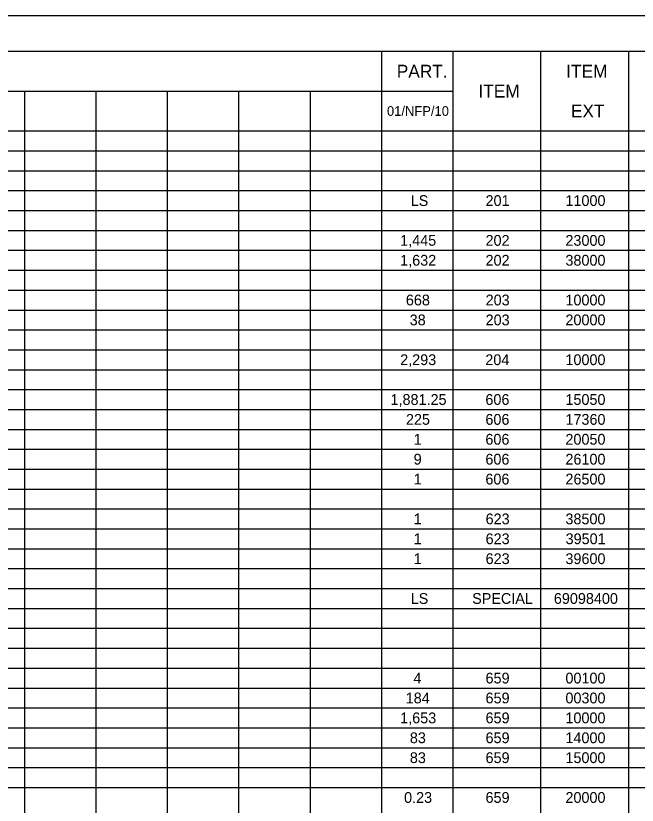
# Model space of a CAD drawing. Extents: x -31.7 to 37.3, y 0 to 22.
# Drawn here: x 9.42 to 18.16, y 10.89 to 22 of the extents above; entities that cross this region are included whole.
import ezdxf

# ---------------------------------------------------------------- set-up
doc = ezdxf.new("R2010")
doc.units = 0
for name, color, linetype in [('SH_Border', 7, 'Continuous'), ('SH_Cut_Line', 7, 'Continuous'), ('SH_Data', 7, 'Continuous'), ('SH_Text', 7, 'Continuous')]:
    doc.layers.add(name, color=color, linetype=linetype)

msp = doc.modelspace()

# ---------------------------------------------------------------- linework, layer by layer
at = {"layer": 'SH_Border'}
msp.add_lwpolyline([(1.5, 21.5), (33.5, 21.5), (33.5, 0.5), (1.5, 0.5)], close=True, dxfattribs=at)
at = {"layer": 'SH_Cut_Line'}
msp.add_lwpolyline([(0, 0), (34, 0), (34, 22), (0, 22)], close=True, dxfattribs=at)
at = {"layer": 'SH_Data'}
for p, q in [((1.5, 21.5), (32.001, 21.5)), ((14.56, 21.5), (14.56, 0.502)), ((15.565, 21.5), (15.565, 0.502)), ((16.8, 21.5), (16.8, 0.502)), ((18.035, 21.5), (18.035, 0.502)), ((1.5, 20.94), (15.565, 20.94)), ((9.537, 20.94), (9.537, 0.502)), ((10.542, 20.94), (10.542, 0.502)), ((11.546, 20.94), (11.546, 0.502)), ((12.551, 20.94), (12.551, 0.502)), ((13.556, 20.94), (13.556, 0.502)), ((1.5, 20.38), (32.001, 20.38)), ((1.5, 20.1), (32.001, 20.1)), ((1.5, 19.82), (32.001, 19.82)), ((1.5, 19.54), (32.001, 19.54)), ((1.5, 19.26), (32.001, 19.26)), ((1.5, 18.98), (32.001, 18.98)), ((1.5, 18.7), (32.001, 18.7)), ((1.5, 18.42), (32.001, 18.42)), ((1.5, 18.14), (32.001, 18.14)), ((1.5, 17.86), (32.001, 17.86)), ((1.5, 17.58), (32.001, 17.58)), ((1.5, 17.3), (32.001, 17.3)), ((1.5, 17.02), (32.001, 17.02)), ((1.5, 16.74), (32.001, 16.74)), ((1.5, 16.46), (32.001, 16.46)), ((1.5, 16.18), (32.001, 16.18)), ((1.5, 15.9), (32.001, 15.9)), ((1.5, 15.62), (32.001, 15.62)), ((1.5, 15.34), (32.001, 15.34)), ((1.5, 15.061), (32.001, 15.061)), ((1.5, 14.781), (32.001, 14.781)), ((1.5, 14.501), (32.001, 14.501)), ((1.5, 14.221), (32.001, 14.221)), ((1.5, 13.941), (32.001, 13.941)), ((1.5, 13.661), (32.001, 13.661)), ((1.5, 13.381), (32.001, 13.381)), ((1.5, 13.101), (32.001, 13.101)), ((1.5, 12.821), (32.001, 12.821)), ((1.5, 12.541), (32.001, 12.541)), ((1.5, 12.261), (32.001, 12.261)), ((1.5, 11.981), (32.001, 11.981)), ((1.5, 11.701), (32.001, 11.701)), ((1.5, 11.421), (32.001, 11.421)), ((1.5, 11.141), (32.001, 11.141))]:
    msp.add_line(p, q, dxfattribs=at)

# ---------------------------------------------------------------- texts
at = {"layer": 'SH_Text'}
for s, height, p in [('PART.', 0.1818, (14.776, 21.129)), ('ITEM', 0.1818, (17.16, 21.129)), ('ITEM', 0.1818, (15.925, 20.849)), ('01/NFP/10', 0.1364, (14.638, 20.592)), ('EXT', 0.1818, (17.226, 20.569)), ('LS', 0.1515, (14.972, 19.324)), ('201', 0.1515, (16.025, 19.324)), ('11000', 0.1515, (17.149, 19.324)), ('1,445', 0.1515, (14.824, 18.764)), ('202', 0.1515, (16.025, 18.764)), ('23000', 0.1515, (17.149, 18.764)), ('1,632', 0.1515, (14.824, 18.484)), ('202', 0.1515, (16.025, 18.484)), ('38000', 0.1515, (17.149, 18.484)), ('668', 0.1515, (14.904, 17.925)), ('203', 0.1515, (16.026, 17.925)), ('10000', 0.1515, (17.149, 17.925)), ('38', 0.1515, (14.958, 17.645)), ('203', 0.1515, (16.026, 17.645)), ('20000', 0.1515, (17.149, 17.645)), ('2,293', 0.1515, (14.824, 17.085)), ('204', 0.1515, (16.022, 17.085)), ('10000', 0.1515, (17.149, 17.085)), ('1,881.25', 0.1515, (14.688, 16.525)), ('606', 0.1515, (16.023, 16.525)), ('15050', 0.1515, (17.149, 16.525)), ('225', 0.1515, (14.905, 16.245)), ('606', 0.1515, (16.023, 16.245)), ('17360', 0.1515, (17.149, 16.245)), ('1', 0.152, (15.014, 15.965)), ('606', 0.1515, (16.023, 15.965)), ('20050', 0.1515, (17.149, 15.965)), ('9', 0.152, (15.013, 15.685)), ('606', 0.1515, (16.023, 15.685)), ('26100', 0.1515, (17.149, 15.685)), ('1', 0.152, (15.014, 15.405)), ('606', 0.1515, (16.023, 15.405)), ('26500', 0.1515, (17.149, 15.405)), ('1', 0.152, (15.014, 14.845)), ('623', 0.1515, (16.026, 14.845)), ('38500', 0.1515, (17.149, 14.845)), ('1', 0.152, (15.014, 14.565)), ('623', 0.1515, (16.026, 14.565)), ('39501', 0.1515, (17.151, 14.565)), ('1', 0.152, (15.014, 14.285)), ('623', 0.1515, (16.026, 14.285)), ('39600', 0.1515, (17.149, 14.285)), ('LS', 0.1515, (14.972, 13.725)), ('SPECIAL', 0.1515, (15.836, 13.725)), ('69098400', 0.1515, (16.986, 13.725)), ('4', 0.152, (15.011, 12.605)), ('659', 0.1515, (16.025, 12.605)), ('00100', 0.1515, (17.149, 12.605)), ('184', 0.1515, (14.902, 12.325)), ('659', 0.1515, (16.025, 12.325)), ('00300', 0.1515, (17.149, 12.325)), ('1,653', 0.1515, (14.824, 12.045)), ('659', 0.1515, (16.025, 12.045)), ('10000', 0.1515, (17.149, 12.045)), ('83', 0.1515, (14.96, 11.765)), ('659', 0.1515, (16.025, 11.765)), ('14000', 0.1515, (17.149, 11.765)), ('83', 0.1515, (14.96, 11.485)), ('659', 0.1515, (16.025, 11.485)), ('15000', 0.1515, (17.149, 11.485)), ('0.23', 0.1515, (14.879, 10.925)), ('659', 0.1515, (16.025, 10.925)), ('20000', 0.1515, (17.149, 10.925))]:
    msp.add_text(s, height=height, dxfattribs=at).set_placement(p)

doc.saveas('drawing.dxf')
